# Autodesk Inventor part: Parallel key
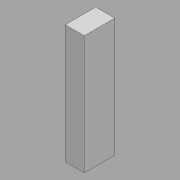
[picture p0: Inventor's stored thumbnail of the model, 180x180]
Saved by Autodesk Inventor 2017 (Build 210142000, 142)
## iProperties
Created: 2016-05
Part Number: Parallel key
Material: Generic
Document SubType Name: Modeling
Designer: CADCIM
Density: 1 g/cm^3
Appearance: Default
Author: CADCIM
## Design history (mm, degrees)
sketch "Sketch1"
  geometry: L1 (0, 0)-(16, 0); L2 (16, 0)-(16, -62.5); L3 (16, -62.5)-(0, -62.5); L4 (0, -62.5)-(0, 0)
  constraints: 8 end point, 2 parallel, 1 horizontal, 1 perpendicular
  dimensions: "d0" = 62.5 distance of L3.end L1.start; "d1" = 16 distance of L2.end L3.end
extrude "Extrusion1" new body sketch "Sketch1" distance "d2" = 10; taper "d3" = 0 deg
body "Solid1"
